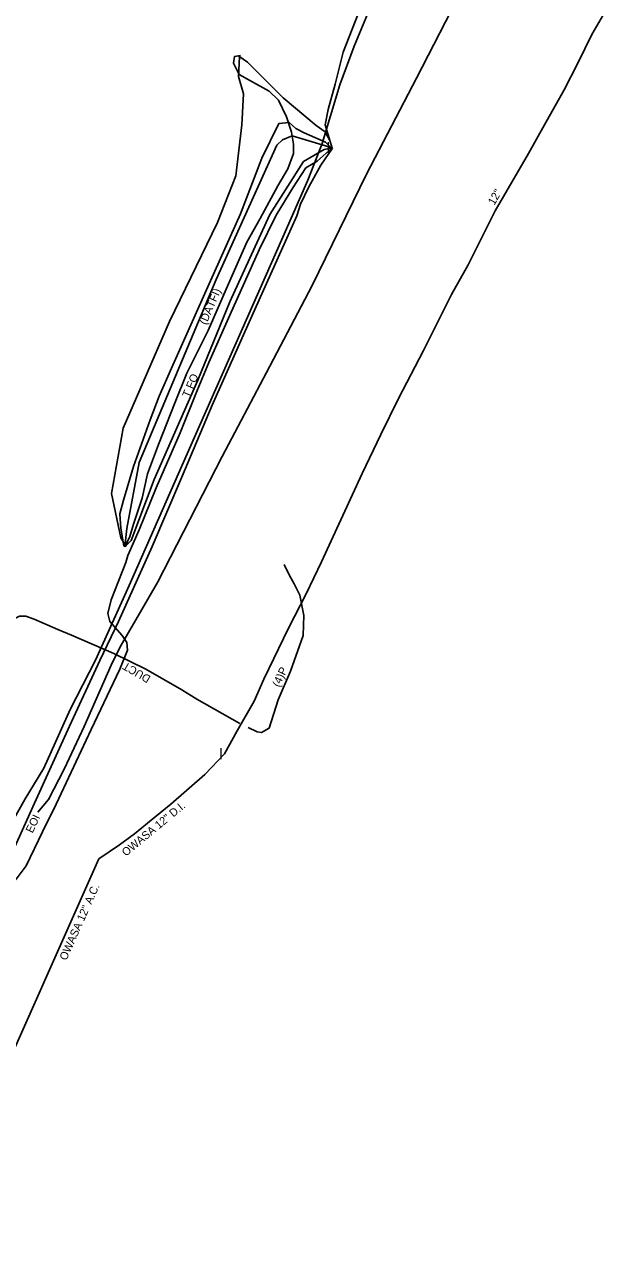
# Model space of a CAD drawing. Extents: x 1975707 to 1978340, y 778386 to 782872.
# Drawn here: x 1977746 to 1978037, y 781726 to 782334 of the extents above; entities that cross this region are included whole.
import ezdxf

# ---------------------------------------------------------------- set-up
doc = ezdxf.new("R2010")
doc.units = 0
for name, color, linetype in [('Exist Utilities Gas UG Line SUE', 7, 'Continuous'), ('Exist Utilities Other Unknown UG SUE', 7, 'Continuous'), ('Exist Utilities Other Unknown UG SUE Text', 7, 'Continuous'), ('Exist Utilities Power UG Cable SUE', 7, 'Continuous'), ('Exist Utilities Power UG Cable SUE Text', 7, 'Continuous'), ('Exist Utilities Telephone Manhole CELL', 7, 'Continuous'), ('Exist Utilities Telephone UG Cable SUE', 7, 'Continuous'), ('Exist Utilities Telephone UG Cable SUE Text', 7, 'Continuous'), ('Exist Utilities Telephone UG Conduit', 7, 'Continuous'), ('Exist Utilities Telephone UG Conduit SUE', 7, 'Continuous'), ('Exist Utilities Telephone UG FO', 7, 'Continuous'), ('Exist Utilities Telephone UG FO SUE', 7, 'Continuous'), ('Exist Utilities TV UG Cable SUE', 7, 'Continuous'), ('Exist Utilities TV UG Cable SUE Text', 7, 'Continuous'), ('Exist Utilities Water UG Line', 7, 'Continuous'), ('Exist Utilities Water UG Line SUE', 7, 'Continuous'), ('Exist Utilities Water UG Line SUE Text', 7, 'Continuous'), ('Exist Utilities Water UG Line Text', 7, 'Continuous'), ('Exist Utilities Water Valve CELL', 7, 'Continuous')]:
    doc.layers.add(name, color=color, linetype=linetype)

msp = doc.modelspace()

# ---------------------------------------------------------------- linework, layer by layer
at = {"layer": 'Exist Utilities Gas UG Line SUE'}
for points in [[(1977798.5, 782053.16), (1977833.6, 782133.1), (1977875.2, 782227.34), (1977887.75, 782255.77), (1977894.94, 782274.13), (1977903.77, 782303.41), (1977910.8, 782322.74), (1977919.99, 782344.83), (1977933.19, 782369.41), (1977938.26, 782381.19)], [(1977668.39, 781766.32), (1977671.98, 781772.85), (1977674.8, 781780.48), (1977685.73, 781808.33), (1977697.64, 781840.3), (1977707.4, 781866.15), (1977713.19, 781881.35), (1977729.19, 781915.92), (1977746.51, 781946.62), (1977755.79, 781961.89), (1977768.95, 781991.29), (1977781.68, 782015.93), (1977798.5, 782053.16)]]:
    msp.add_lwpolyline(points, dxfattribs=at)
at = {"layer": 'Exist Utilities Other Unknown UG SUE'}
msp.add_lwpolyline([(1977752.86, 781940), (1977758.18, 781946.26), (1977766.02, 781961.37), (1977776.02, 781982.78), (1977789.38, 782013.37), (1977793.97, 782022.59), (1977812.55, 782054.69), (1977844.82, 782117.67), (1977867.03, 782159.71), (1977889.68, 782202.79), (1977917.21, 782259.1), (1977941.96, 782306.88), (1977965.1, 782351.95)], dxfattribs=at)
at = {"layer": 'Exist Utilities Power UG Cable SUE'}
for points in [[(1977857.89, 781982.31), (1977862.34, 781980.14), (1977864.5, 781979.73), (1977868.37, 781981.95), (1977872.86, 781996.04), (1977878.97, 782010.42), (1977885.32, 782028.27), (1977885.78, 782038.19), (1977883.63, 782048.31), (1977880.88, 782054.11), (1977878.35, 782058.59), (1977875.83, 782063.64)], [(1977705.92, 781958.8), (1977709.41, 781967.34), (1977715.04, 781977.6), (1977721.15, 781991.05), (1977728.44, 782007.99), (1977734.25, 782023), (1977739.11, 782033.39), (1977741.31, 782036.74), (1977743.62, 782037.88), (1977746.89, 782037.93), (1977750.97, 782036.42), (1977762.85, 782031.24), (1977769.67, 782028.47)], [(1977853.78, 781984.32), (1977832.31, 781996.34), (1977824.73, 782001.1), (1977806.76, 782011.33), (1977790.8, 782019.2), (1977769.67, 782028.47)]]:
    msp.add_lwpolyline(points, dxfattribs=at)
at = {"layer": 'Exist Utilities Telephone UG Cable SUE'}
for points in [[(1977930.02, 782373.17), (1977923.84, 782361.5), (1977915.83, 782346.85), (1977905.37, 782319.79), (1977901.33, 782303.8), (1977897.89, 782291.22), (1977896.42, 782283.42), (1977899.86, 782271.77)], [(1977789.48, 782046.07), (1977796.73, 782064.64), (1977797.77, 782068.14), (1977803.39, 782080.98), (1977811.94, 782101.96), (1977823.84, 782129.55), (1977832.41, 782150.68), (1977838.16, 782164.61), (1977848.78, 782188.39), (1977863.45, 782221.04), (1977871.88, 782238.4), (1977880.23, 782252.01), (1977886.77, 782261.99), (1977892.34, 782265.34), (1977899.9, 782271.94)], [(1977679.07, 781763.54), (1977689.96, 781787.2), (1977695.87, 781801.26), (1977700.42, 781814.79), (1977705.85, 781829.14), (1977720.51, 781860.35), (1977729.5, 781883.1), (1977738.5, 781903.66), (1977742.02, 781906.51), (1977746.96, 781913.13), (1977755.2, 781930.1), (1977761.94, 781943.95), (1977779.38, 781981.26), (1977793.81, 782011.4), (1977797.68, 782020.93), (1977797.19, 782024.78), (1977794.86, 782028.15), (1977788.74, 782035.25), (1977787.71, 782039.23), (1977789.48, 782046.07)]]:
    msp.add_lwpolyline(points, dxfattribs=at)
at = {"layer": 'Exist Utilities Telephone UG Conduit'}
msp.add_lwpolyline([(1977796.4, 782072.68), (1977799.38, 782075.74), (1977810.91, 782106.26), (1977832.81, 782155.82), (1977848.8, 782195.04), (1977868.76, 782238.65), (1977885.48, 782265.15), (1977895.82, 782271.08), (1977899.9, 782271.94)], dxfattribs=at)
at = {"layer": 'Exist Utilities Telephone UG Conduit SUE'}
msp.add_lwpolyline([(1977853.21, 782317.86), (1977857.53, 782314.8), (1977875.43, 782296.93), (1977891.82, 782283.11), (1977896.42, 782280.03), (1977898.61, 782275.62), (1977899.87, 782271.9)], dxfattribs=at)
at = {"layer": 'Exist Utilities Telephone UG FO'}
msp.add_lwpolyline([(1977796.34, 782072.62), (1977797.24, 782081.79), (1977803.46, 782114.67), (1977841.91, 782206.2), (1977872.22, 782273.25), (1977875.11, 782276.01), (1977879.85, 782277.97), (1977899.9, 782271.94)], dxfattribs=at)
at = {"layer": 'Exist Utilities Telephone UG FO SUE'}
for points in [[(1977796.34, 782072.62), (1977795.74, 782073), (1977794.31, 782081.81), (1977793.77, 782089.07), (1977795.61, 782095.86), (1977800.58, 782112.66), (1977808.85, 782136.07), (1977813.35, 782147.82), (1977819.52, 782161.91), (1977836.22, 782199.22), (1977854.04, 782238.96), (1977864.76, 782266.86), (1977873.28, 782284.14), (1977878.31, 782284.57), (1977881.73, 782281.64), (1977885.94, 782279.46), (1977896.61, 782274.84), (1977899.84, 782271.56)], [(1977672.36, 781765.03), (1977674.96, 781771.77), (1977676.89, 781778.99), (1977697.61, 781825.34), (1977710.72, 781854.49), (1977734.52, 781907.45), (1977751.07, 781944.38), (1977768.57, 781982.98), (1977783.74, 782015.74), (1977793.06, 782035.18), (1977809.88, 782072.76), (1977824.65, 782106.96), (1977839.88, 782143.31), (1977859.65, 782187.84), (1977876.52, 782225.41), (1977882.2, 782238.05), (1977884.02, 782243.79), (1977888.14, 782252.52), (1977894.24, 782263.3), (1977900.02, 782271.75)]]:
    msp.add_lwpolyline(points, dxfattribs=at)
at = {"layer": 'Exist Utilities TV UG Cable SUE'}
for points in [[(1977796.89, 782072.74), (1977794.34, 782077.02), (1977789.69, 782099.29), (1977795.44, 782131.79), (1977805.48, 782154.92), (1977818.52, 782185.22), (1977842.54, 782234.64), (1977851.76, 782258.01), (1977854.68, 782283.48), (1977855.57, 782298.99), (1977853.13, 782307.59), (1977853.5, 782317.45)], [(1977796.4, 782072.68), (1977798.73, 782077.66), (1977800.61, 782083.88), (1977804.95, 782096.92), (1977807.63, 782109.05), (1977813.11, 782123.7), (1977821.35, 782144.94), (1977827.3, 782159.31), (1977837.93, 782180.65), (1977848.11, 782204.04), (1977857.29, 782224.76), (1977863.87, 782236.7), (1977872.72, 782253.02), (1977877.65, 782261.47), (1977880.47, 782269.15), (1977880.57, 782273.83), (1977879.47, 782279.84), (1977877.03, 782287.41), (1977873.02, 782295.79), (1977868.32, 782300.36), (1977859.01, 782305.56), (1977853.45, 782308.57), (1977850.51, 782314.3), (1977851.05, 782317.61), (1977853.99, 782318.12)], [(1977796.4, 782072.68), (1977798.73, 782077.66), (1977800.61, 782083.88), (1977804.95, 782096.92), (1977807.63, 782109.05), (1977813.11, 782123.7), (1977821.35, 782144.94), (1977827.3, 782159.31), (1977837.93, 782180.65), (1977848.11, 782204.04), (1977857.29, 782224.76), (1977863.87, 782236.7), (1977872.72, 782253.02), (1977877.65, 782261.47), (1977880.47, 782269.15), (1977880.57, 782273.83), (1977879.47, 782279.84), (1977877.03, 782287.41), (1977873.02, 782295.79), (1977868.32, 782300.36), (1977859.01, 782305.56), (1977853.45, 782308.57), (1977850.51, 782314.3), (1977851.05, 782317.61), (1977853.99, 782318.12)]]:
    msp.add_lwpolyline(points, dxfattribs=at)
at = {"layer": 'Exist Utilities Water UG Line'}
msp.add_lwpolyline([(1977033.01, 780162.16), (1977078.89, 780218.01), (1977118.85, 780269.44), (1977152.93, 780317.27), (1977195.65, 780383.62), (1977231.05, 780446.62), (1977272.65, 780536.29), (1977304.07, 780614.89), (1977344.97, 780723.4), (1977386.53, 780838.5), (1977390.79, 780850.63), (1977405.46, 780895.39), (1977441.08, 781000.27), (1977484.84, 781129.87), (1977538.87, 781282.1), (1977619.4, 781510.83), (1977666.59, 781637.15), (1977711.39, 781751.55), (1977726.04, 781788.03), (1977783.22, 781916.57)], dxfattribs=at)
at = {"layer": 'Exist Utilities Water UG Line SUE'}
msp.add_lwpolyline([(1977783.22, 781916.57), (1977793.68, 781923.53), (1977801.16, 781929.05), (1977811.26, 781937.4), (1977819.24, 781943.87), (1977836.32, 781958.72), (1977846.1, 781969.15), (1977852.36, 781980.63), (1977860.9, 781995.44), (1977865.79, 782006.36), (1977877.96, 782031.95), (1977886.9, 782049.03), (1977894.56, 782065.13), (1977914.87, 782109.19), (1977924.16, 782128.68), (1977933.07, 782146.74), (1977945.45, 782170.68), (1977959.51, 782198.73), (1977967.79, 782213.48), (1977981.37, 782240.57), (1977997.93, 782269.2), (1978005.97, 782283.55), (1978015.84, 782301.06), (1978022.62, 782314.25), (1978029.59, 782328.7), (1978036.51, 782340.57)], dxfattribs=at)

# ---------------------------------------------------------------- texts
at = {"layer": 'Exist Utilities Other Unknown UG SUE Text'}
msp.add_text('EOI', height=4, rotation=64.61646, dxfattribs=at).set_placement((1977750.14, 781929.17))
at = {"layer": 'Exist Utilities Power UG Cable SUE Text'}
for s, rotation, p in [('DUCT', 149.74346, (1977809.53, 782007.7)), ('(4)P', 64.59245, (1977873.35, 782002.12))]:
    msp.add_text(s, height=4, rotation=rotation, dxfattribs=at).set_placement(p)
at = {"layer": 'Exist Utilities Telephone Manhole CELL'}
msp.add_text('l', height=5.5, dxfattribs=at).set_placement((1977897.15, 782269.19))
at = {"layer": 'Exist Utilities Telephone UG Cable SUE Text'}
msp.add_text('T FO', height=4, rotation=67.02699, dxfattribs=at).set_placement((1977828.46, 782146.79))
at = {"layer": 'Exist Utilities TV UG Cable SUE Text'}
msp.add_text('(DATFI)', height=4, rotation=66.48811, dxfattribs=at).set_placement((1977836.87, 782183.23))
at = {"layer": 'Exist Utilities Water UG Line SUE Text'}
for s, rotation, p in [('12"', 60.48205, (1977980.88, 782243.03)), ('OWASA 12" D.I.', 39.59745, (1977796.8, 781917.65))]:
    msp.add_text(s, height=4, rotation=rotation, dxfattribs=at).set_placement(p)
at = {"layer": 'Exist Utilities Water UG Line Text'}
msp.add_text('OWASA 12" A.C.', height=4, rotation=66.01981, dxfattribs=at).set_placement((1977767.06, 781865.49))
at = {"layer": 'Exist Utilities Water Valve CELL'}
msp.add_text('I', height=5.62, dxfattribs=at).set_placement((1977843.29, 781966.33))

doc.saveas('drawing.dxf')
